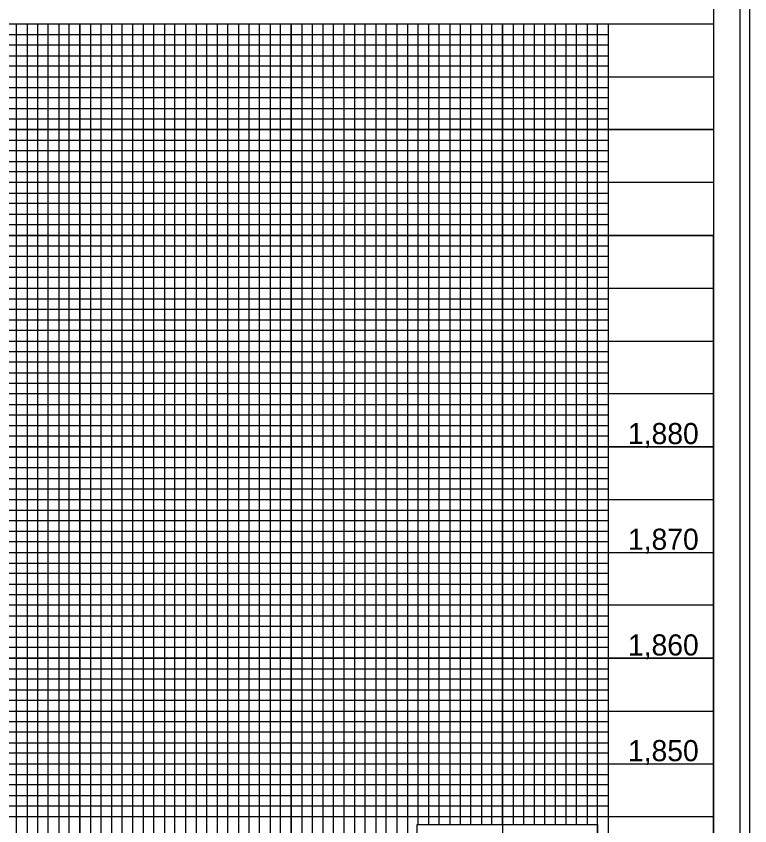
# Model space of a CAD drawing. Extents: x 557032 to 558840, y 515971 to 517218.
# Drawn here: x 558369.3 to 558716.5, y 516288.9 to 516671.8 of the extents above; entities that cross this region are included whole.
import ezdxf

# ---------------------------------------------------------------- set-up
doc = ezdxf.new("R2010")
doc.units = 0
for name, color, linetype in [('Exist Vertical Profile Vertical Axis Label', 7, 'Continuous'), ('Prop DSN Text', 7, 'Continuous'), ('Scratch_Level_5', 7, 'Continuous'), ('Sheet DOT Grid CELL', 7, 'Continuous'), ('Sheet Layout Profile Border Port 2', 7, 'Continuous'), ('Sheet Plot Border Inside CELL', 7, 'Continuous'), ('Sheet Plot Border Outside CELL', 7, 'Continuous'), ('Sheet Profile CELL', 7, 'Continuous'), ('Sheet Profile Grid Major CELL', 7, 'Continuous'), ('Sheet Profile Grid Middle CELL', 7, 'Continuous'), ('Sheet Profile Grid Minor CELL', 7, 'Continuous')]:
    doc.layers.add(name, color=color, linetype=linetype)

msp = doc.modelspace()

# ---------------------------------------------------------------- linework, layer by layer
at = {"layer": 'Prop DSN Text'}
for p, q in [((558559.12, 516289.56), (558644.45, 516289.56)), ((558559.12, 516213.17), (558559.12, 516289.56)), ((558644.45, 516289.56), (558644.45, 516213.17))]:
    msp.add_line(p, q, dxfattribs=at)
at = {"layer": 'Scratch_Level_5'}
msp.add_lwpolyline([(558074.45, 516168.17), (558699.34, 516168.17), (558699.34, 516568.17), (558074.45, 516568.17)], close=True, dxfattribs=at)
at = {"layer": 'Sheet DOT Grid CELL'}
for p, q in [((557199.45, 516668.17), (558699.34, 516668.17)), ((558399.45, 516668.17), (558399.45, 516168.17)), ((558449.45, 516668.17), (558449.45, 516168.17)), ((558499.45, 516668.17), (558499.45, 516168.17)), ((558549.45, 516668.17), (558549.45, 516168.17)), ((558599.45, 516668.17), (558599.45, 516168.17)), ((558649.45, 516668.17), (558649.45, 516168.17)), ((557199.45, 516618.17), (558699.34, 516618.17)), ((557199.45, 516568.17), (558699.34, 516568.17)), ((557199.45, 516518.17), (558699.34, 516518.17)), ((557199.45, 516468.17), (558699.34, 516468.17)), ((557199.45, 516418.17), (558699.34, 516418.17)), ((557199.45, 516368.17), (558699.34, 516368.17)), ((557199.45, 516318.17), (558699.34, 516318.17))]:
    msp.add_line(p, q, dxfattribs=at)
at = {"layer": 'Sheet Layout Profile Border Port 2'}
msp.add_lwpolyline([(557249.45, 516668.17), (558649.45, 516668.17), (558649.45, 516168.17), (557249.45, 516168.17)], close=True, dxfattribs=at)
at = {"layer": 'Sheet Plot Border Inside CELL'}
msp.add_lwpolyline([(557045.45, 516140.62), (558711.95, 516140.62), (558711.95, 517195.72), (557045.45, 517195.72)], close=True, dxfattribs=at)
at = {"layer": 'Sheet Plot Border Outside CELL'}
msp.add_lwpolyline([(557032.45, 516118.17), (558716.45, 516118.17), (558716.45, 517218.17), (557032.45, 517218.17)], close=True, dxfattribs=at)
at = {"layer": 'Sheet Profile CELL'}
msp.add_line((557199.45, 516668.17), (558699.45, 516668.17), dxfattribs=at)
msp.add_lwpolyline([(558699.45, 517193.17), (557199.45, 517193.17), (557199.45, 516143.17), (558699.45, 516143.17)], close=True, dxfattribs=at)
at = {"layer": 'Sheet Profile Grid Major CELL'}
for p, q in [((558399.45, 516668.17), (558449.45, 516668.17)), ((558499.45, 516668.17), (558549.45, 516668.17)), ((558599.45, 516668.17), (558649.45, 516668.17))]:
    msp.add_line(p, q, dxfattribs=at)
for points in [[(558349.45, 516168.17), (558399.45, 516168.17), (558399.45, 516668.17), (558449.45, 516668.17), (558449.45, 516168.17), (558499.45, 516168.17), (558499.45, 516668.17), (558549.45, 516668.17), (558549.45, 516168.17), (558599.45, 516168.17), (558599.45, 516168.17), (558599.45, 516263.76)], [(558599.45, 516289.56), (558599.45, 516668.17), (558649.45, 516668.17), (558649.45, 516168.17)], [(558699.45, 516618.17), (557199.45, 516618.17)], [(558699.45, 516568.17), (557199.45, 516568.17), (557199.45, 516518.17), (558699.45, 516518.17)], [(558699.45, 516468.17), (557199.45, 516468.17), (557199.45, 516418.17), (558699.45, 516418.17)], [(558699.45, 516368.17), (557199.45, 516368.17), (557199.45, 516318.17), (558699.45, 516318.17)]]:
    msp.add_lwpolyline(points, dxfattribs=at)
at = {"layer": 'Sheet Profile Grid Middle CELL'}
for p, q in [((558324.45, 516668.17), (558374.45, 516668.17)), ((558374.45, 516668.17), (558374.45, 516168.17)), ((558424.45, 516168.17), (558424.45, 516668.17)), ((558424.45, 516668.17), (558474.45, 516668.17)), ((558474.45, 516668.17), (558474.45, 516168.17)), ((558524.45, 516168.17), (558524.45, 516668.17)), ((558524.45, 516668.17), (558574.45, 516668.17)), ((558574.45, 516668.17), (558574.45, 516289.56)), ((558624.45, 516289.56), (558624.45, 516668.17))]:
    msp.add_line(p, q, dxfattribs=at)
for points in [[(557199.45, 516643.17), (558699.45, 516643.17)], [(558699.45, 516593.17), (557199.45, 516593.17), (557199.45, 516543.17), (558699.45, 516543.17)], [(558699.45, 516493.17), (557199.45, 516493.17), (557199.45, 516443.17), (558699.45, 516443.17)], [(558699.45, 516393.17), (557199.45, 516393.17), (557199.45, 516343.17), (558699.45, 516343.17)], [(558699.45, 516293.17), (557199.45, 516293.17), (557199.45, 516243.17), (558699.45, 516243.17)]]:
    msp.add_lwpolyline(points, dxfattribs=at)
at = {"layer": 'Sheet Profile Grid Minor CELL'}
for p, q in [((557249.45, 516663.17), (558649.45, 516663.17)), ((558649.45, 516658.17), (557249.45, 516658.17)), ((557249.45, 516653.17), (558649.45, 516653.17)), ((558649.45, 516648.17), (557249.45, 516648.17)), ((557249.45, 516638.17), (558649.45, 516638.17)), ((558649.45, 516633.17), (557249.45, 516633.17)), ((557249.45, 516628.17), (558649.45, 516628.17)), ((558649.45, 516623.17), (557249.45, 516623.17)), ((557249.45, 516613.17), (558649.45, 516613.17)), ((558649.45, 516608.17), (557249.45, 516608.17)), ((557249.45, 516603.17), (558649.45, 516603.17)), ((558649.45, 516598.17), (557249.45, 516598.17)), ((557249.45, 516588.17), (558649.45, 516588.17)), ((558649.45, 516583.17), (557249.45, 516583.17)), ((557249.45, 516578.17), (558649.45, 516578.17)), ((558649.45, 516573.17), (557249.45, 516573.17)), ((557249.45, 516563.17), (558649.45, 516563.17)), ((558649.45, 516558.17), (557249.45, 516558.17)), ((557249.45, 516553.17), (558649.45, 516553.17)), ((558649.45, 516548.17), (557249.45, 516548.17)), ((557249.45, 516538.17), (558649.45, 516538.17)), ((558649.45, 516533.17), (557249.45, 516533.17)), ((557249.45, 516528.17), (558649.45, 516528.17)), ((558649.45, 516523.17), (557249.45, 516523.17)), ((557249.45, 516513.17), (558649.45, 516513.17)), ((558649.45, 516508.17), (557249.45, 516508.17)), ((557249.45, 516503.17), (558649.45, 516503.17)), ((558649.45, 516498.17), (557249.45, 516498.17)), ((557249.45, 516488.17), (558649.45, 516488.17)), ((558649.45, 516483.17), (557249.45, 516483.17)), ((557249.45, 516478.17), (558649.45, 516478.17)), ((558649.45, 516473.17), (557249.45, 516473.32)), ((557249.45, 516463.17), (558649.45, 516463.17)), ((558649.45, 516458.17), (557249.45, 516458.17)), ((557249.45, 516453.17), (558649.45, 516453.17)), ((558649.45, 516448.17), (557249.45, 516448.17)), ((557249.45, 516438.17), (558649.45, 516438.17)), ((558649.45, 516433.17), (557249.45, 516433.17)), ((557249.45, 516428.17), (558649.45, 516428.17)), ((558649.45, 516423.17), (557249.45, 516423.17)), ((557249.45, 516413.17), (558649.45, 516413.17)), ((558649.45, 516408.17), (557249.45, 516408.17)), ((557249.45, 516403.17), (558649.45, 516403.17)), ((558649.45, 516398.17), (557249.45, 516398.17)), ((557249.45, 516388.17), (558649.45, 516388.17)), ((558649.45, 516383.17), (557249.45, 516383.17)), ((557249.45, 516378.17), (558649.45, 516378.17)), ((558649.45, 516373.17), (557249.45, 516373.17)), ((557249.45, 516363.17), (558649.45, 516363.17)), ((558649.45, 516358.17), (557249.45, 516358.17)), ((557249.45, 516353.17), (558649.45, 516353.17)), ((558649.45, 516348.17), (557249.45, 516348.17)), ((557249.45, 516338.17), (558649.45, 516338.17)), ((558649.45, 516333.17), (557249.45, 516333.17)), ((557249.45, 516328.17), (558649.45, 516328.17)), ((558649.45, 516323.17), (557249.45, 516323.17)), ((557249.45, 516313.17), (558649.45, 516313.17)), ((558649.45, 516308.17), (557249.45, 516308.17)), ((557249.45, 516303.17), (558649.45, 516303.17)), ((558649.45, 516298.17), (557249.45, 516298.17))]:
    msp.add_line(p, q, dxfattribs=at)
for points in [[(558364.45, 516168.17), (558369.45, 516168.17), (558369.45, 516668.17), (558379.45, 516668.17), (558379.45, 516168.17), (558384.45, 516168.17), (558384.45, 516668.17), (558389.45, 516668.17), (558389.45, 516168.17)], [(558394.45, 516168.17), (558394.45, 516668.17), (558404.45, 516668.17), (558404.45, 516168.17)], [(558409.45, 516168.17), (558409.45, 516668.17), (558414.45, 516668.17), (558414.45, 516168.17)], [(558419.45, 516168.17), (558419.45, 516668.17), (558429.45, 516668.17), (558429.45, 516168.17)], [(558434.45, 516168.17), (558434.45, 516668.17), (558439.45, 516668.17), (558439.45, 516168.17)], [(558444.45, 516168.17), (558444.45, 516668.17), (558454.45, 516668.17), (558454.45, 516168.17)], [(558459.45, 516168.17), (558459.45, 516668.17), (558464.45, 516668.17), (558464.45, 516168.17)], [(558469.45, 516168.17), (558469.45, 516668.17), (558479.45, 516668.17), (558479.45, 516168.17)], [(558484.45, 516168.17), (558484.45, 516668.17), (558489.45, 516668.17), (558489.45, 516168.17)], [(558494.45, 516168.17), (558494.45, 516668.17), (558504.45, 516668.17), (558504.45, 516168.17)], [(558509.45, 516168.17), (558509.45, 516668.17), (558514.45, 516668.17), (558514.45, 516168.17)], [(558519.45, 516168.17), (558519.45, 516668.17), (558529.45, 516668.17), (558529.45, 516168.17)], [(558534.45, 516168.17), (558534.45, 516668.17), (558539.45, 516668.17), (558539.45, 516168.17)], [(558544.45, 516168.17), (558544.45, 516668.17), (558554.45, 516668.17), (558554.45, 516168.17)], [(558559.45, 516289.56), (558559.45, 516668.17), (558564.45, 516668.17), (558564.45, 516289.56)], [(558569.45, 516289.56), (558569.45, 516668.17), (558579.45, 516668.17), (558579.45, 516289.56)], [(558584.45, 516289.56), (558584.45, 516668.17), (558589.45, 516668.17), (558589.45, 516289.56)], [(558594.45, 516289.56), (558594.45, 516668.17), (558604.45, 516668.17), (558604.45, 516289.56)], [(558609.45, 516289.56), (558609.45, 516668.17), (558614.45, 516668.17), (558614.45, 516289.56)], [(558619.45, 516289.56), (558619.45, 516668.17), (558629.45, 516668.17), (558629.45, 516289.56)], [(558634.45, 516289.56), (558634.45, 516668.17), (558639.45, 516668.17), (558639.45, 516289.56)], [(558639.45, 516263.76), (558639.45, 516168.17), (558644.45, 516168.17), (558644.45, 516668.17), (558649.45, 516668.17)]]:
    msp.add_lwpolyline(points, dxfattribs=at)

# ---------------------------------------------------------------- texts
at = {"layer": 'Exist Vertical Profile Vertical Axis Label'}
for s, p in [('1,880', (558658.81, 516469.42)), ('1,870', (558658.81, 516419.42)), ('1,860', (558658.81, 516369.42)), ('1,850', (558658.81, 516319.42))]:
    msp.add_text(s, height=10, dxfattribs=at).set_placement(p)

doc.saveas('drawing.dxf')
